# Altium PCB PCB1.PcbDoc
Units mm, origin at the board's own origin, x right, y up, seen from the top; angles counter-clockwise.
Board outline 49 x 49 mm, 2 copper layers (Top Layer, Bottom Layer); 24 components, 46 nets, 156 pads, 23 vias.
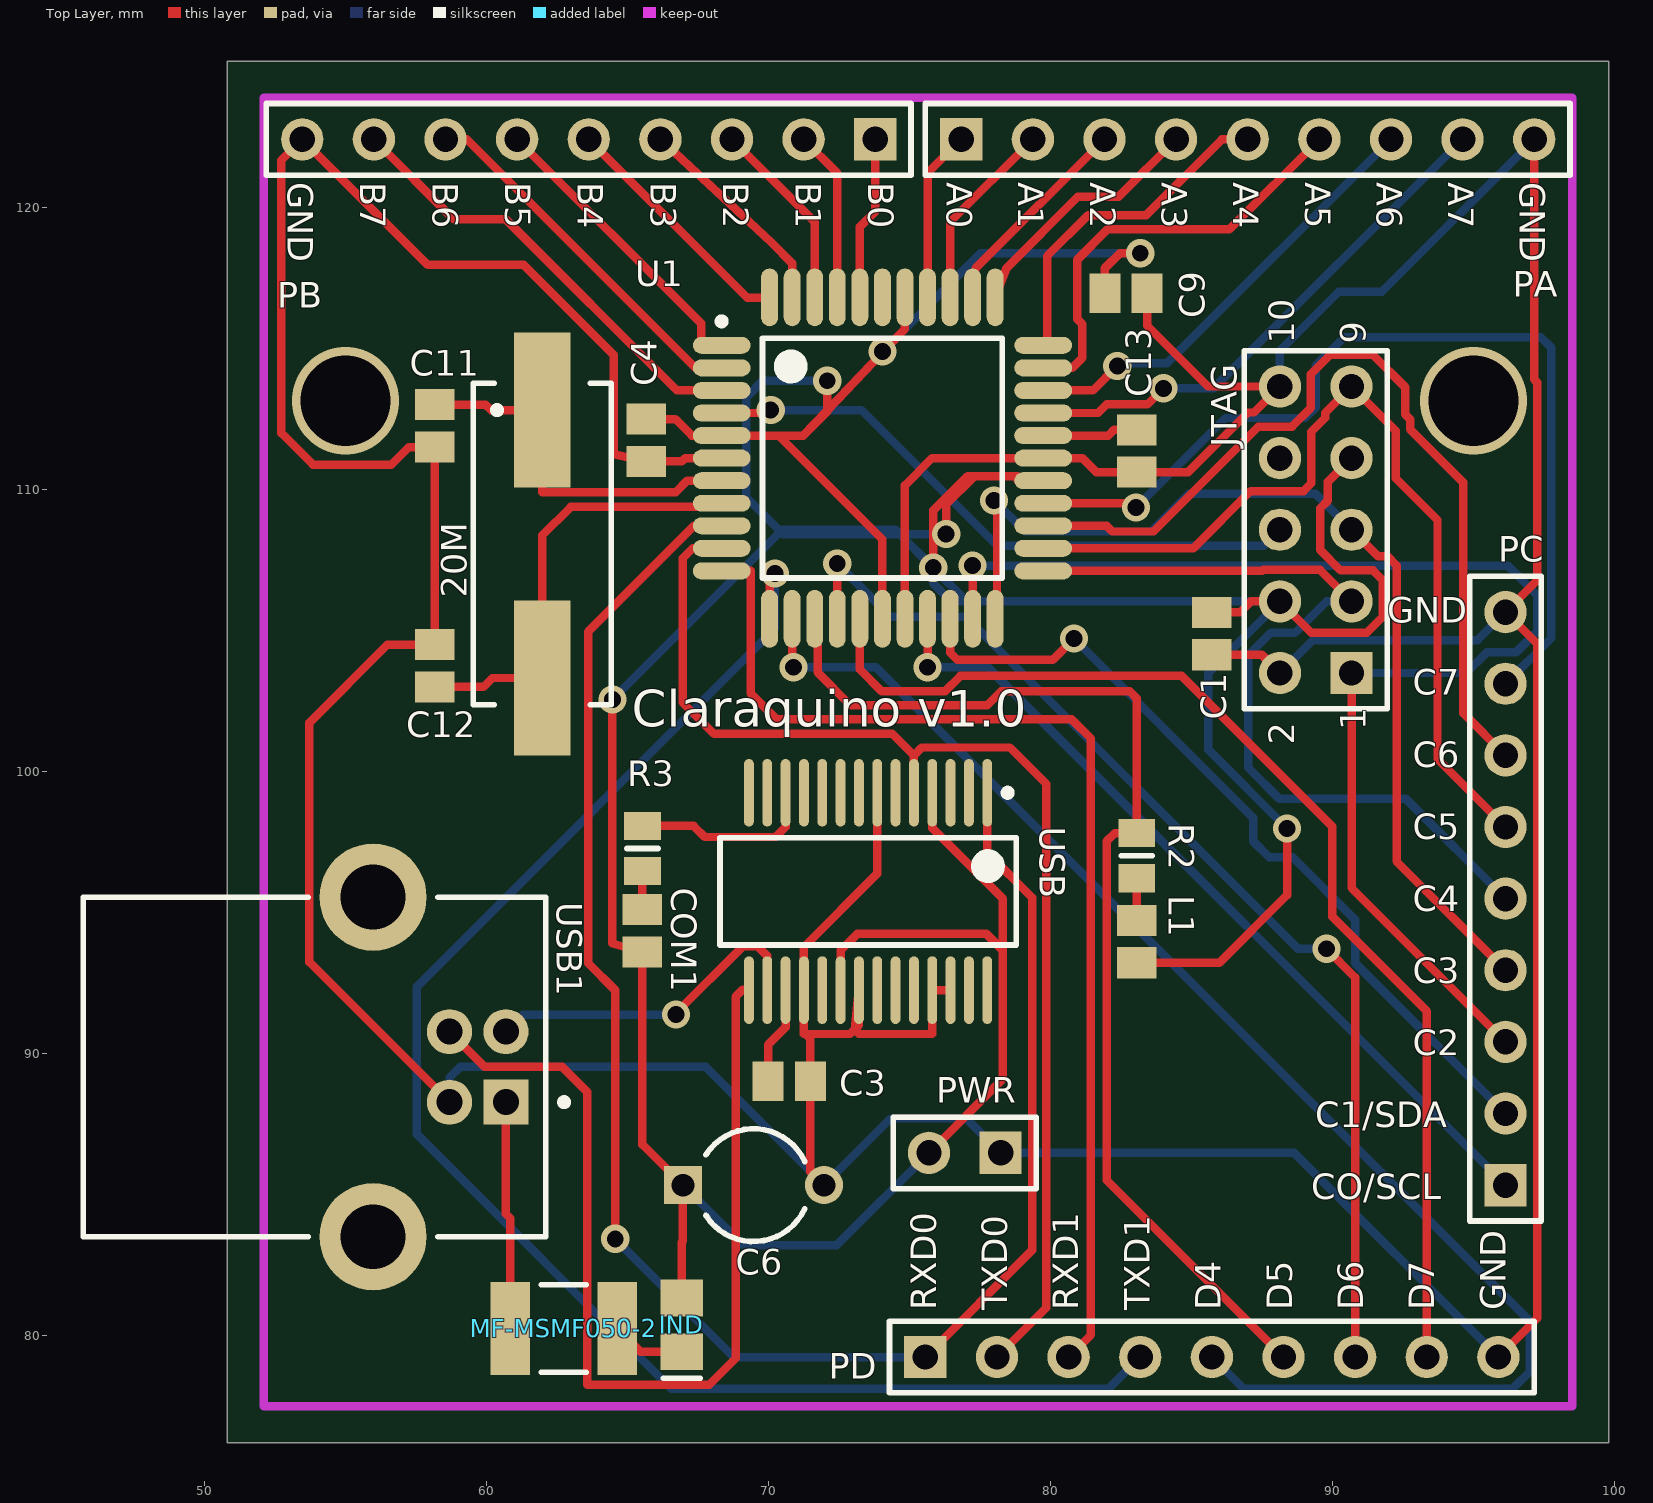
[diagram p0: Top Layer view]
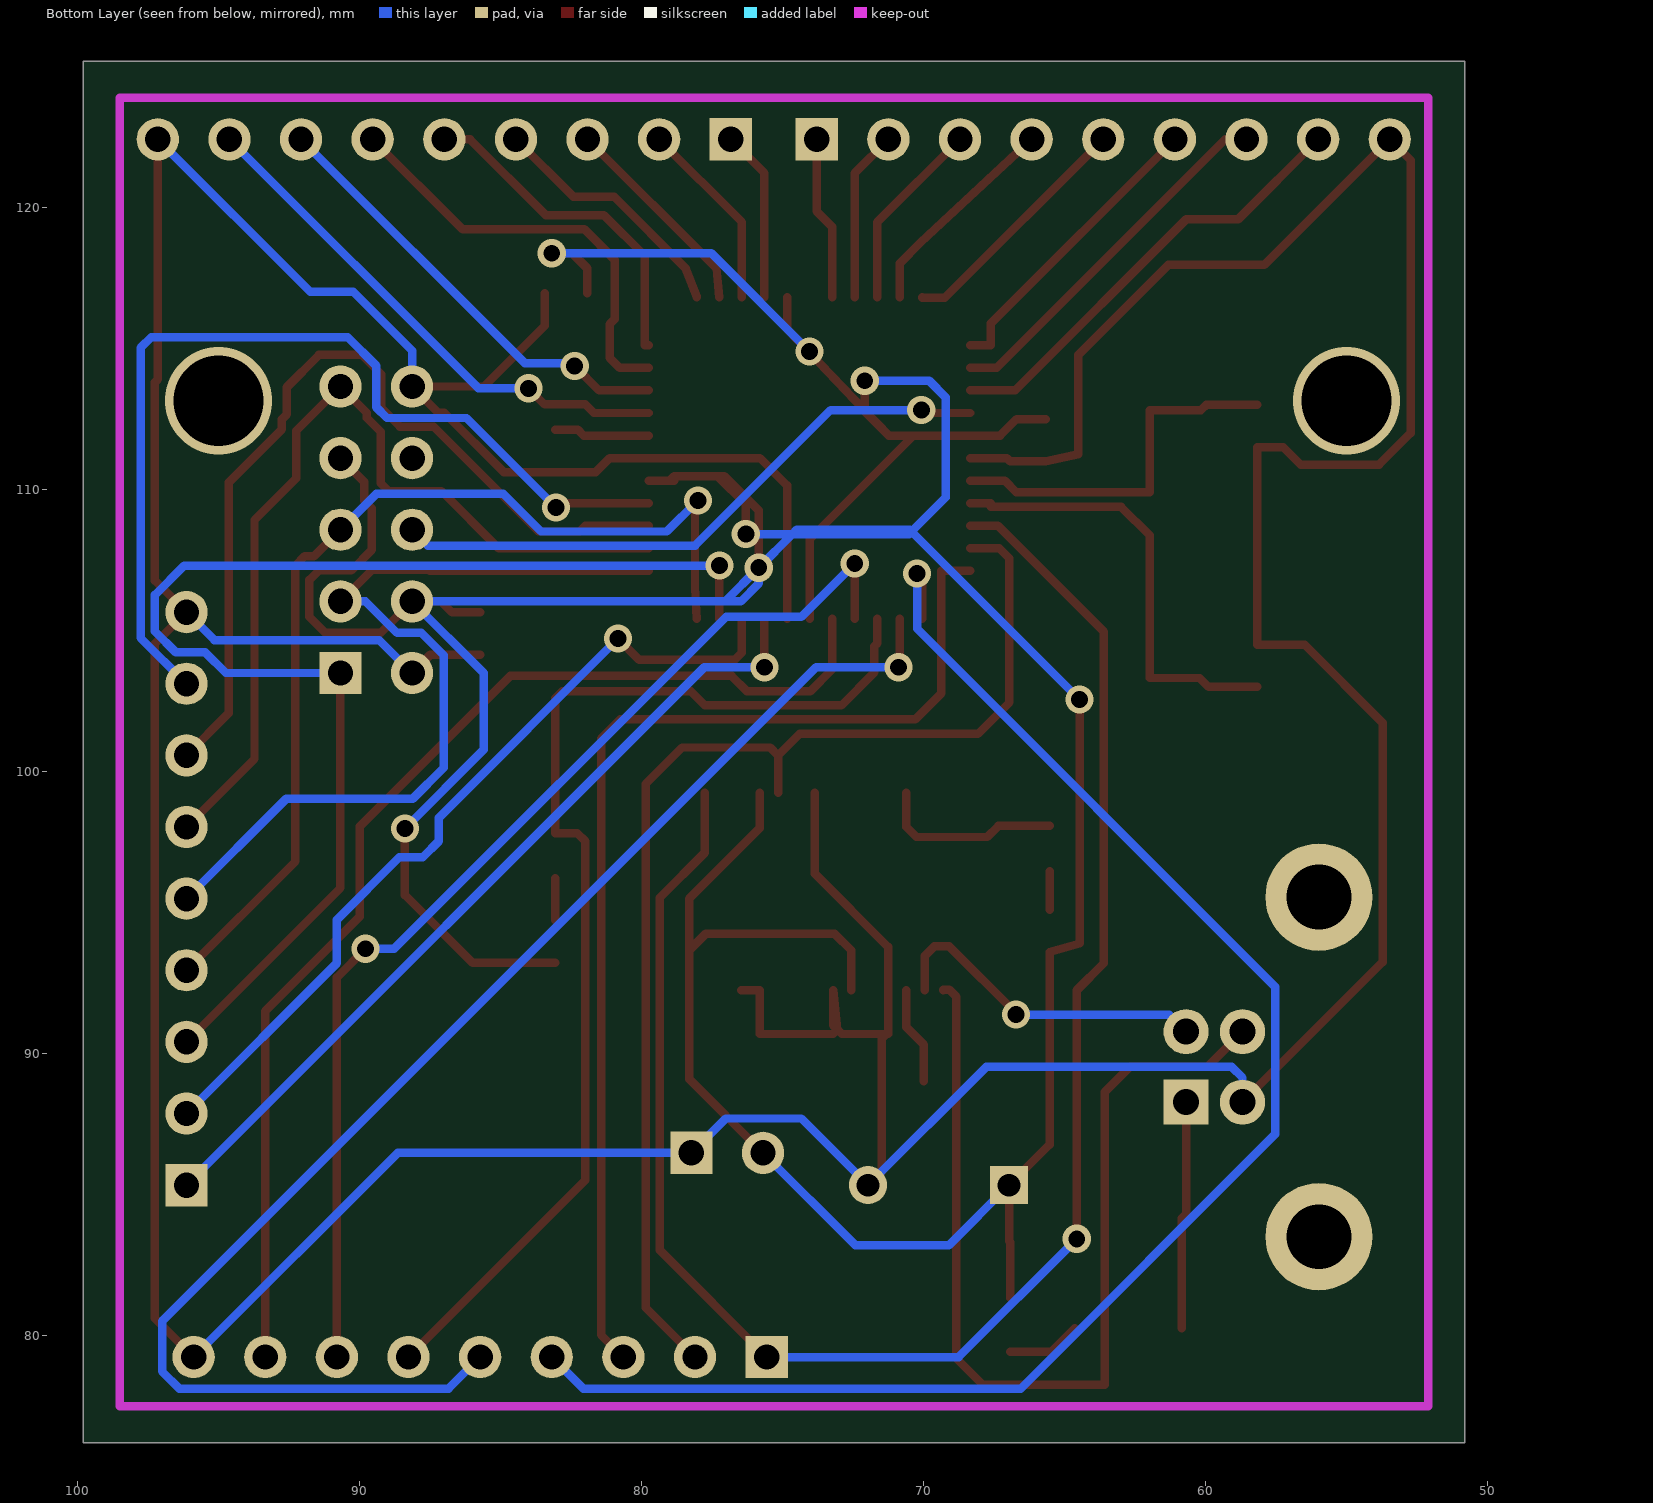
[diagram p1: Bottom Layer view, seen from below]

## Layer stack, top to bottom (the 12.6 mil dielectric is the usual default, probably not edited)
Top Layer: signal copper 0.0356
Dielectric: dielectric 0.32, FR-4, Dk 4.8
Bottom Layer: signal copper 0.0356

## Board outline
50.8,76.2 99.8,76.2 99.8,125.2 50.8,125.2

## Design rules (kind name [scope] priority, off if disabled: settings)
Clearance [All] p1: gap=0.2
PolygonConnect [All] p1: connectstyle=Relief reliefconductorwidth=0.254 reliefentries=4 polygonreliefangle="90 Angle"
RoutingVias [All] p1: holewidth=0.6 width=1 viastyle="Through Hole" minholewidth=0.711 minwidth=1.27 maxholewidth=0.711 maxwidth=1.27
SilkscreenOverComponentPads [All] p1: minsilkscreentomaskgap=0.254
SolderMaskExpansion [All] p1: expansion=0.102
Width [All] p1: maxlimit=3 minlimit=0.3 preferedwidth=0.3
27 further rules are at their usual default settings.

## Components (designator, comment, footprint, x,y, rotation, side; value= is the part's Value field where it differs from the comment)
20M "20M" HC49/4H_SMX 61.976,108.077 r270 top (schematic designator XTAL1)
C1 "100nF" CAPC2012L 85.725,104.902 r90 top
C3 "100nF" CAPC2012L 70.739,89.027 r180 top
C4 "100nF" CAPC2012L 65.659,111.76 r90 top
C6 "Cap2" CAPR5-4X5 69.469,85.344 r0 top
C9 "100nF" CAPC2012L 82.677,116.967 r180 top
C11 "18p" CAPC2012L 58.166,112.268 r90 top
C12 "18p" CAPC2012L 58.166,103.759 r270 top
C13 "100nF" CAPC2012L 83.058,111.379 r90 top
COM1 "LED2" CAPC2012L 65.532,94.361 r90 top
IND "MH2029-300Y" 0805 66.929,80.391 r90 top
JTAG "Header 5X2" HDR2X5 90.678,103.505 r90 top
L1 "LED2" CAPC2012L 83.058,93.98 r90 top
MF-MSMF050-2 "Fusible" RESC4532L 62.738,80.264 r0 top
PA "Header 9" HDR1X9 76.835,122.428 r0 top
PB "Header 9" HDR1X9 73.787,122.428 r180 top
PC "Header 9" HDR1X9 96.139,85.344 r90 top
PD "Header 9" HDR1X9 75.565,79.248 r0 top
PWR "Header 2" HDR1X2 78.232,86.487 r180 top
R2 "Res2" RESC2012L 83.058,97.028 r270 top
R3 "Res2" RESC2012L 65.532,97.282 r270 top
U1 "ATmega164PA-AU" 44A_M 74.041,111.125 r0 top
USB "FT232RL-Tube" SSOP-28_M 73.533,95.758 r270 top
USB1 "USB_CONNECTOR_B" USB2.5-2H4D 59.69,89.535 r180 top

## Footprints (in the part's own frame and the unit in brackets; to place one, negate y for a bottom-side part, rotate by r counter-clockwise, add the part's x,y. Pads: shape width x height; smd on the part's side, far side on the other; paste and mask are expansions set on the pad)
44A_M [mm] "Thin QFP, 44-Leads, Body 10x10mm, Pitch 0.8mm, IPC Low Density"
  oval 2.05x0.6 smd: 1(-5.7,4) 2(-5.7,3.2) 3(-5.7,2.4) 4(-5.7,1.6) 5(-5.7,0.8) 6(-5.7,0) 7(-5.7,-0.8) 8(-5.7,-1.6) 9(-5.7,-2.4) 10(-5.7,-3.2) 11(-5.7,-4) 23(5.7,-4) 24(5.7,-3.2) 25(5.7,-2.4) 26(5.7,-1.6) 27(5.7,-0.8) 28(5.7,0) 29(5.7,0.8) 30(5.7,1.6) 31(5.7,2.4) 32(5.7,3.2) 33(5.7,4)
  oval 0.6x2.05 smd: 12(-4,-5.7) 13(-3.2,-5.7) 14(-2.4,-5.7) 15(-1.6,-5.7) 16(-0.8,-5.7) 17(0,-5.7) 18(0.8,-5.7) 19(1.6,-5.7) 20(2.4,-5.7) 21(3.2,-5.7) 22(4,-5.7) 34(4,5.7) 35(3.2,5.7) 36(2.4,5.7) 37(1.6,5.7) 38(0.8,5.7) 39(0,5.7) 40(-0.8,5.7) 41(-1.6,5.7) 42(-2.4,5.7) 43(-3.2,5.7) 44(-4,5.7)
  silkscreen extent -5.82,-4.25 4.25,4.97, body extent -5,-5 5,5, height 1.2
0805 [mm] "Chip Capacitor; Body 2.0 x 1.2 mm (LxW typ)"
  rect 1.3x1.5 smd: 1(-0.95,0) 2(0.95,0)
  silkscreen extent -1.9,-0.65 -1.9,0.65
CAPC2012L [mm] "Chip Capacitor, Body 2.0x1.3mm, IPC High Density"
  rect 1.1x1.4 smd: 1(-0.75,0) 2(0.75,0)
  body extent -1.1,-0.72 1.1,0.72, height 1.1
CAPR5-4X5 [mm] "Capacitor; 2 Leads"
  rect 1.35x1.35 hole 0.8: 1(-2.5,0)
  round 1.35 hole 0.8: 2(2.5,0)
  silkscreen extent -1.69,-2 1.82,2
HC49/4H_SMX [mm] "Quartz Crystal, SM; Body 13.4 (inc. leads) x 4.9 mm (LxW max)"
  rect 5.5x2 smd: 1(-4.75,0) 2(4.75,0)
  silkscreen extent -5.7,-2.45 5.7,2.45
HDR1X2 [mm] "Connector; Header; 2 Position"
  rect 1.5x1.5 hole 0.9: 1(0,0)
  round 1.5 hole 0.9: 2(2.54,0)
  silkscreen extent -1.27,-1.27 3.81,1.27
HDR1X9 [mm] "Connector; Header; 9 Position"
  rect 1.5x1.5 hole 0.9: 1(0,0)
  round 1.5 hole 0.9: 2(2.54,0) 3(5.08,0) 4(7.62,0) 5(10.16,0) 6(12.7,0) 7(15.24,0) 8(17.78,0) 9(20.32,0)
  silkscreen extent -1.27,-1.27 21.59,1.27
HDR2X5 [mm] "Connector; Header; 5x2 Position"
  rect 1.5x1.5 hole 0.9: 1(0,0)
  round 1.5 hole 0.9: 2(0,2.54) 3(2.54,0) 4(2.54,2.54) 5(5.08,0) 6(5.08,2.54) 7(7.62,0) 8(7.62,2.54) 9(10.16,0) 10(10.16,2.54)
  silkscreen extent -1.27,-1.27 11.43,3.81
RESC2012L [mm] "Chip Resistor, Body 2.0x1.3mm, IPC High Density"
  rect 1x1.3 smd: 1(-0.8,0) 2(0.8,0)
  silkscreen extent 0,-0.55 0,0.55, body extent -1.07,-0.7 1.07,0.7, height 0.65
RESC4532L [mm] "Chip Resistor, Body 4.5x3.2mm, IPC High Density"
  rect 1.4x3.3 smd: 1(-1.9,0) 2(1.9,0)
  silkscreen extent -0.8,-1.55 0.8,1.55, body extent -2.4,-1.7 2.4,1.7, height 0.71
SSOP-28_M [mm] "SOP, 28-Leads, Body 10.2x5.3mm, Pitch 0.65mm, IPC Low Density"
  oval 2.4x0.35 smd: 1(-3.5,4.225) 2(-3.5,3.575) 3(-3.5,2.925) 4(-3.5,2.275) 5(-3.5,1.625) 6(-3.5,0.975) 7(-3.5,0.325) 8(-3.5,-0.325) 9(-3.5,-0.975) 10(-3.5,-1.625) 11(-3.5,-2.275) 12(-3.5,-2.925) 13(-3.5,-3.575) 14(-3.5,-4.225) 15(3.5,-4.225) 16(3.5,-3.575) 17(3.5,-2.925) 18(3.5,-2.275) 19(3.5,-1.625) 20(3.5,-0.975) 21(3.5,-0.325) 22(3.5,0.325) 23(3.5,0.975) 24(3.5,1.625) 25(3.5,2.275) 26(3.5,2.925) 27(3.5,3.575) 28(3.5,4.225)
  silkscreen extent -3.62,-5.25 1.9,5.25, body extent -2.8,-5.25 2.8,5.25, height 2
USB2.5-2H4D [mm] "Connector; USB1.1, Type B, Thru-Hole; 4 Position; Right Angle"
  rect 1.6x1.6 hole 0.92: 1(-1,1.25)
  round 1.6 hole 0.92: 2(-1,-1.25) 3(1,-1.25) 4(1,1.25)
  round 3.8 hole 2.3: 5(3.71,6.02) 6(3.71,-6.02)
  silkscreen extent -3.18,-6.02 13.99,6.02, body extent -2.41,-6.02 13.99,6.02, height 11.1

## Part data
20M: library part CRYSTAL, "Crystal"
C1 C3 C4 C9 C11 C12 C13: library part CAP, "Capacitor"
C6: "Capacitor"
COM1 L1: "Typical RED, GREEN, YELLOW, AMBER GaAs LED"
IND: library part Inductor, "Inductor"
JTAG: "Header, 5-Pin, Dual row"
MF-MSMF050-2: library part "Fuse 2", "Fuse"
PA PB PC PD: "Header, 9-Pin"
PWR: "Header, 2-Pin"
R2 R3: "Resistor"
U1: "8-bit AVR Microcontroller, 16KB Flash, 512 Bytes EEPROM, 1KB SRAM, 44-pin TQFP, Industrial Grade (-40°C to 85°C)"
USB: "USB UART Asynchronous Serial Data Transfer Chip, SSOP-28, Tube"

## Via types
v1: diameter 1, hole 0.6, Top Layer to Bottom Layer, 21 vias
v2: diameter 3.8, hole 3.2, Top Layer to Bottom Layer, 2 vias

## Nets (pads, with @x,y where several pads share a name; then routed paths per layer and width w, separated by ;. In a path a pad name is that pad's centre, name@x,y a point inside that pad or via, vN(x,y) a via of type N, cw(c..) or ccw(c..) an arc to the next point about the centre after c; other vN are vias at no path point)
+3.3: C3.2 USB.17 | length 3.5
  Top Layer w0.3: C3.2 69.989,90.322 70.608,90.941 USB.17
+5: C1.2 C4.2 C6.1 C9.2 COM1.1 IND.2 JTAG.4 JTAG.7 L1.1 PWR.2 U1.5 U1.17 U1.27 U1.38 USB.4 USB.20 | length 179.1
  Top Layer w0.3: v1(64.465,102.565) 64.465,93.916 COM1.1 65.532,86.781 C6.1 66.969,83.352 66.929,83.312 IND.2 ; C4.2 66.7,112.51 67.285,111.925 U1.5 70.358,111.925 ; v1(72.085,113.868) 72.085,112.818 ; USB.20 72.558,93.665 73.152,94.259 77.724,94.259 78.308,93.675 ; U1.17 74.041,108.242 70.358,111.925 ; v1(74.041,114.91) 74.841,115.71 ; U1.38 74.841,115.71 ; PWR.2 78.308,89.103 78.308,93.675 ; USB.4 75.808,98.004 78.308,95.504 78.308,93.675 ; v1(75.844,107.239) 75.844,109.271 77.064,110.49 77.318,110.49 ; v1(76.302,108.433) 76.302,109.474 77.318,110.49 ; U1.27 U1.27@79.007,110.325 ; C9.2 81.927,117.856 82.46,118.389 v1(83.185,118.389) ; L1.1 85.991,93.23 88.392,95.631 v1(88.392,97.993) ; C1.2 86.716,105.652 87.109,106.045 JTAG.4 89.256,104.927 91.211,104.927 91.778,105.494 91.778,106.807 91.44,107.145 90.289,107.145 89.56,107.874 89.56,109.344 89.832,109.615 89.832,110.279 JTAG.7 ; 70.358,111.925 71.234,111.925 ; 71.234,111.925 72.085,112.818 ; 71.234,111.925 72.085,112.776 72.085,112.818 ; 72.085,112.818 74.061,114.891 74.841,115.71 ; 77.318,110.49 U1.27@78.842,110.49 ; U1.27@78.842,110.49 78.842,110.325 U1.27@79.007,110.325 ; U1.27@78.842,110.49 U1.27@79.007,110.325
  Bottom Layer w0.3: v1(64.465,102.565) 70.421,108.521 ; C6.1 69.103,83.21 72.415,83.21 PWR.2 ; v1(72.085,113.868) 69.799,113.868 69.215,113.284 69.215,109.728 70.421,108.521 ; v1(74.041,114.91) 77.521,118.389 v1(83.185,118.389) ; v1(76.302,108.433) 74.651,108.433 ; v1(88.392,97.993) 85.598,100.787 85.598,103.505 JTAG.4 77.038,106.045 ; 70.421,108.521 70.51,108.433 74.651,108.433 ; 70.421,108.521 70.485,108.585 74.498,108.585 74.651,108.433 ; 74.651,108.433 v1(75.844,107.239) ; v1(75.844,107.239) 75.844,106.68 76.479,106.045 77.038,106.045 ; v1(75.844,107.239) 77.038,106.045
/LED1: PD.6 R2.1 U1.14 | length 40.9
  Top Layer w0.3: U1.14 71.641,104.558 71.741,104.458 71.741,103.532 72.915,102.358 77.755,102.358 78.247,102.85 82.817,102.85 83.058,102.609 R2.1 82.283,97.828 81.991,97.536 81.991,85.522 PD.6
/LED2: R3.1 USB.12 | length 6.6
  Top Layer w0.3: R3.1 67.348,98.082 67.742,97.688 70.252,97.688 70.608,98.044 USB.12
/RESET: JTAG.6 U1.4 | length 22.1
  Top Layer w0.3: U1.4 69.977,112.725 v1(70.079,112.827)
  Bottom Layer w0.3: v1(70.079,112.827) 73.297,112.827 78.102,108.022 87.575,108.022 JTAG.6
A0: PA.1 U1.37 | length 6.1
  Top Layer w0.3: U1.37 75.641,121.234 PA.1
A1: PA.2 U1.36 | length 6.8
  Top Layer w0.3: U1.36 76.441,119.494 PA.2
A2: PA.3 U1.35 | length 7.5
  Top Layer w0.3: U1.35 77.343,117.856 PA.3
A3: PA.4 U1.34 | length 9
  Top Layer w0.3: U1.34 78.435,117.856 80.975,120.396 82.423,120.396 PA.4
A4: PA.5 U1.33 | length 12.1
  Top Layer w0.3: U1.33 79.883,115.125 79.883,118.288 81.335,119.739 83.392,119.739 86.081,122.428 PA.5
A5: PA.6 U1.32 | length 15.4
  Top Layer w0.3: U1.32 80.772,114.325 81.128,114.681 81.128,115.875 80.95,116.053 80.95,118.161 82.028,119.239 86.346,119.239 PA.6
A6: PA.7 U1.31 | length 16
  Top Layer w0.3: U1.31 81.508,113.525 v1(82.371,114.388)
  Bottom Layer w0.3: v1(82.371,114.388) 82.479,114.496 84.143,114.496 PA.7
A7: PA.8 U1.30 | length 18.9
  Top Layer w0.3: U1.30 81.687,112.725 81.991,113.029 83.439,113.029 v1(84.011,113.601)
  Bottom Layer w0.3: v1(84.011,113.601) 85.788,113.601 PA.8
B0: PB.1 U1.40 | length 5.8
  Top Layer w0.3: U1.40 73.241,119.329 73.787,119.875 PB.1
B1: PB.2 U1.41 | length 6.1
  Top Layer w0.3: PB.2 72.441,121.234 U1.41
B2: PB.3 U1.42 | length 6.8
  Top Layer w0.3: PB.3 71.641,119.494 U1.42
B3: PB.4 U1.43 | length 7.6
  Top Layer w0.3: PB.4 70.104,118.77 70.841,118.033 U1.43
B4: PB.5 U1.44 | length 8.7
  Top Layer w0.3: PB.5 69.24,116.815 70.041,116.815 U1.44
B5/MOSI: PB.6 U1.1 | length 10.7
  Top Layer w0.3: PB.6 67.615,115.9 67.615,115.125 U1.1
B6/MISO: PB.7 U1.2 | length 13.2
  Top Layer w0.3: PB.7 59.309,122.428 67.412,114.325 U1.2
B7/SCK: PB.8 U1.3 | length 16
  Top Layer w0.3: PB.8 58.841,119.594 60.682,119.594 66.751,113.525 U1.3
C0/SCL: PC.1 U1.19 | length 29.8
  Top Layer w0.3: v1(75.641,103.708) U1.19
  Bottom Layer w0.3: v1(75.641,103.708) 77.775,103.708 PC.1
C1/SDA: PC.2 U1.20 | length 29.7
  Top Layer w0.3: U1.20 76.441,104.229 76.7,103.971 80.081,103.971 v1(80.835,104.724)
  Bottom Layer w0.3: v1(80.835,104.724) 87.193,98.367 87.193,97.536 87.754,96.975 88.585,96.975 90.811,94.748 90.811,93.212 PC.2
C2: JTAG.1 PC.3 U1.21 | length 46.2
  Top Layer w0.3: U1.21 v1(77.241,107.315) ; JTAG.1 90.678,95.885 PC.3
  Bottom Layer w0.3: v1(77.241,107.315) 96.215,107.315 97.257,106.274 97.257,104.978 96.52,104.242 95.479,104.242 94.742,103.505 JTAG.1
C3: JTAG.5 PC.4 U1.22 | length 36.5
  Top Layer w0.3: v1(78.003,109.626) 78.105,109.525 78.105,106.541 U1.22 ; JTAG.5 91.618,107.645 91.948,107.645 92.278,107.315 92.278,96.825 PC.4
  Bottom Layer w0.3: v1(78.003,109.626) 79.107,108.522 83.566,108.522 84.899,109.855 89.408,109.855 JTAG.5
C4: JTAG.3 PC.5 U1.23 | length 30.9
  Top Layer w0.3: U1.23 87.516,107.125 87.554,107.163 89.56,107.163 JTAG.3
  Bottom Layer w0.3: JTAG.3 89.789,106.045 88.671,104.927 87.808,104.927 87.02,104.14 87.02,100.14 88.116,99.044 92.599,99.044 PC.5
C5: JTAG.9 PC.6 U1.24 | length 32.4
  Top Layer w0.3: U1.24 85.065,107.925 87.096,109.957 88.976,109.957 89.256,110.236 89.256,112.065 89.738,112.547 89.738,112.725 JTAG.9 92.25,112.093 92.25,110.407 93.726,108.931 93.726,100.457 PC.6
C6: PC.7 U1.25 | length 31.2
  Top Layer w0.3: U1.25 81.991,108.725 82.193,108.522 83.656,108.522 87.376,112.243 88.57,112.243 89.238,112.911 89.238,114.105 89.916,114.783 91.44,114.783 92.583,113.64 92.583,112.674 92.761,112.497 92.761,112.141 94.64,110.261 94.64,102.083 PC.7
C7: PC.8 U1.26 | length 34.2
  Top Layer w0.3: U1.26 82.88,109.525 v1(83.033,109.372)
  Bottom Layer w0.3: v1(83.033,109.372) 86.208,112.547 89.027,112.547 89.408,112.928 89.408,114.402 90.424,115.418 97.384,115.418 97.765,115.037 97.765,104.75 PC.8
D4: PD.5 U1.13 | length 51.2
  Top Layer w0.3: U1.13 70.841,103.759 v1(70.891,103.708)
  Bottom Layer w0.3: v1(70.891,103.708) 73.812,103.708 97.003,80.518 97.003,78.74 96.393,78.13 86.843,78.13 PD.5
D6: PD.7 U1.15 | length 39.9
  Top Layer w0.3: U1.15 v1(72.441,107.391) ; v1(89.789,93.726) 90.805,92.71 PD.7
  Bottom Layer w0.3: v1(72.441,107.391) 74.336,105.496 77.003,105.496 88.773,93.726 v1(89.789,93.726)
D7: PD.8 U1.16 | length 41.5
  Top Layer w0.3: U1.16 73.241,103.632 74.015,102.858 76.264,102.858 76.81,103.403 84.655,103.403 89.992,98.066 89.992,94.869 93.345,91.516 PD.8
GND: C1.1 C3.1 C4.1 C6.2 C9.1 C11.1 C12.1 C13.1 JTAG.2 JTAG.10 PA.9 PB.9 PC.9 PD.9 PWR.1 U1.6 U1.18 U1.28 USB1.4 USB.7 USB.18 USB.21 USB.25 USB.26 | length 232.5
  Top Layer w0.3: USB1.4 53.721,93.254 53.721,101.74 56.49,104.509 C12.1 C11.1 57.252,111.518 56.63,110.896 53.848,110.896 52.73,112.014 52.73,121.691 PB.9 57.912,117.983 61.316,117.983 64.516,114.783 64.516,111.264 C4.1 66.929,111.01 67.044,111.125 U1.6 ; C6.2 71.489,85.824 C3.1 71.489,90.526 71.311,90.703 ; USB.7 73.858,96.393 71.258,93.793 USB.18 71.258,90.757 ; U1.18 74.841,110.16 75.806,111.125 U1.28 81.128,111.125 81.624,110.629 C13.1 84.889,110.629 87.003,112.743 87.216,112.743 JTAG.10 85.586,113.665 83.427,115.824 C9.1 ; USB.26 USB.25 75.808,90.703 73.208,90.703 73.053,90.858 ; C1.1 87.491,104.152 JTAG.2 ; PD.9 97.257,80.62 97.257,104.546 PC.9 97.257,106.782 97.257,113.817 97.155,113.919 PA.9 ; 71.258,90.757 71.311,90.703 ; 71.258,90.757 71.258,90.703 71.311,90.703 ; 71.311,90.703 72.898,90.703 73.053,90.858 ; 73.053,90.858 USB.21 73.208,91.013 73.053,90.858
  Bottom Layer w0.3: USB1.4 58.69,89.154 59.071,89.535 67.778,89.535 C6.2 74.331,87.706 77.013,87.706 PWR.1 88.646,86.487 PD.9 ; JTAG.2 89.306,104.673 95.148,104.673 PC.9 ; JTAG.10 88.138,114.935 90.221,117.018 91.745,117.018 PA.9
NetC11_2: 20M.1 C11.2 U1.7 | length 13.3
  Top Layer w0.3: C11.2 59.969,113.018 60.16,112.827 20M.1 61.976,109.911 66.706,109.911 67.12,110.325 U1.7
NetC12_2: 20M.2 C12.2 U1.8 | length 15.9
  Top Layer w0.3: C12.2 59.893,103.009 60.211,103.327 20M.2 61.976,108.382 62.992,109.398 67.615,109.398 67.615,109.525 U1.8
NetC13_2: C13.2 U1.29 | length 3.4
  Top Layer w0.3: U1.29 82.055,111.925 82.259,112.129 C13.2
NetCOM1_2: COM1.2 R3.2 | length 1.4
  Top Layer w0.3: COM1.2 R3.2
NetIND_1: IND.1 MF-MSMF050-2.2 | length 2.6
  Top Layer w0.3: MF-MSMF050-2.2 65.461,79.441 IND.1
NetL1_2: L1.2 R2.2 | length 1.5
  Top Layer w0.3: L1.2 R2.2
NetMF-MSMF050-2_1: MF-MSMF050-2.1 USB1.1 | length 8.1
  Top Layer w0.3: USB1.1 60.69,84.324 60.838,84.176 MF-MSMF050-2.1
NetUSB1_2: USB1.2 USB.16 | length 11.9
  Top Layer w0.3: v1(66.726,91.389) 66.726,91.446 69.088,93.808 69.622,93.808 69.958,93.472 USB.16
  Bottom Layer w0.3: USB1.2 61.294,91.389 v1(66.726,91.389)
NetUSB1_3: USB1.3 USB.15 | length 35.2
  Top Layer w0.3: USB1.3 59.94,89.535 62.687,89.535 63.576,88.646 63.576,78.257 67.894,78.257 68.834,79.197 68.834,92.024 69.088,92.278 69.308,92.278 USB.15
RXD0: PD.2 U1.10 USB.5 | length 43.3
  Top Layer w0.3: U1.10 67.31,107.925 66.954,107.569 66.954,102.464 68.072,101.346 74.396,101.346 75.158,100.584 ; USB.5 75.158,100.584 ; PD.2 79.858,81.001 79.858,99.568 78.562,100.863 75.437,100.863 75.158,100.584
RXD1: PD.3 U1.11 | length 40.4
  Top Layer w0.3: U1.11 69.367,107.125 69.367,102.784 70.294,101.858 80.756,101.858 81.432,101.182 81.432,80.035 PD.3
TXD0: PD.1 U1.9 USB.1 | length 63.2
  Top Layer w0.3: v1(64.567,83.439) 64.567,92.253 63.602,93.218 63.602,104.966 67.361,108.725 U1.9 ; PD.1 79.35,83.033 79.35,95.538 77.758,97.13 USB.1
  Bottom Layer w0.3: v1(64.567,83.439) 68.758,79.248 PD.1
TXD1: PD.4 U1.12 | length 56.7
  Top Layer w0.3: U1.12 70.041,106.846 v1(70.231,107.036)
  Bottom Layer w0.3: v1(70.231,107.036) 70.231,105.08 57.531,92.38 57.531,87.147 66.548,78.13 82.067,78.13 PD.4
pads on no net: JTAG.8 U1.39 USB1.5 USB1.6 USB.2 USB.3 USB.6 USB.8 USB.9 USB.10 USB.11 USB.13 USB.14 USB.19 USB.22 USB.23 USB.24 USB.27 USB.28
copper on no net:
  other v2: 55,113.157 95,113.157

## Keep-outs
Keep-Out Layer:
  lines w0.3: 52.1,77.5 52.1,123.9 98.5,123.9 98.5,77.5 52.1,77.5

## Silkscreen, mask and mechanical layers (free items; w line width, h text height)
Top Overlay:
  text "GND" at 52.959,120.904 h0.9 r270
  text "B7" at 55.531,120.904 h0.9 r270
  text "B6" at 58.102,120.904 h0.9 r270
  text "B5" at 60.674,120.904 h0.9 r270
  text "B4" at 63.246,120.904 h0.9 r270
  text "B3" at 65.818,120.904 h0.9 r270
  text "B2" at 68.389,120.904 h0.9 r270
  text "B1" at 70.961,120.904 h0.9 r270
  text "B0" at 73.533,120.904 h0.9 r270
  text "A0" at 76.327,120.904 h0.9 r270
  text "A1" at 78.867,120.904 h0.9 r270
  text "A2" at 81.407,120.904 h0.9 r270
  text "A3" at 83.947,120.904 h0.9 r270
  text "A4" at 86.487,120.904 h0.9 r270
  text "A5" at 89.027,120.904 h0.9 r270
  text "A6" at 91.567,120.904 h0.9 r270
  text "A7" at 94.107,120.904 h0.9 r270
  text "GND" at 96.647,120.904 h0.9 r270
  text "GND" at 91.948,105.283 h0.9
  text "C7" at 92.848,102.727 h0.9
  text "Claraquino v1.0" at 65.151,101.6 h1.3
  text "C6" at 92.848,100.171 h0.9
  text "C5" at 92.848,97.615 h0.9
  text "C4" at 92.848,95.059 h0.9
  text "C3" at 92.848,92.504 h0.9
  text "C2" at 92.848,89.948 h0.9
  text "C1/SDA" at 89.399,87.392 h0.9
  text "CO/SCL" at 89.249,84.836 h0.9
  text "RXD0" at 75.946,80.899 h0.9 r90
  text "TXD0" at 78.47,80.899 h0.9 r90
  text "RXD1" at 80.994,80.899 h0.9 r90
  text "TXD1" at 83.518,80.899 h0.9 r90
  text "D4" at 86.042,80.899 h0.9 r90
  text "D5" at 88.567,80.899 h0.9 r90
  text "D6" at 91.091,80.899 h0.9 r90
  text "D7" at 93.615,80.899 h0.9 r90
  text "GND" at 96.139,80.899 h0.9 r90
Drill Drawing:
  text ".LEGEND" at 104.88,81.28 h1.52
  text "Drill Drawing." at 104.88,78.74 h1.52

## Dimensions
52.1,77.5 to 52.1,123.9 on Mechanical 1
52.1,77.5 to 98.5,77.5 on Mechanical 1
